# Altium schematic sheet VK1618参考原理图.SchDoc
size A4
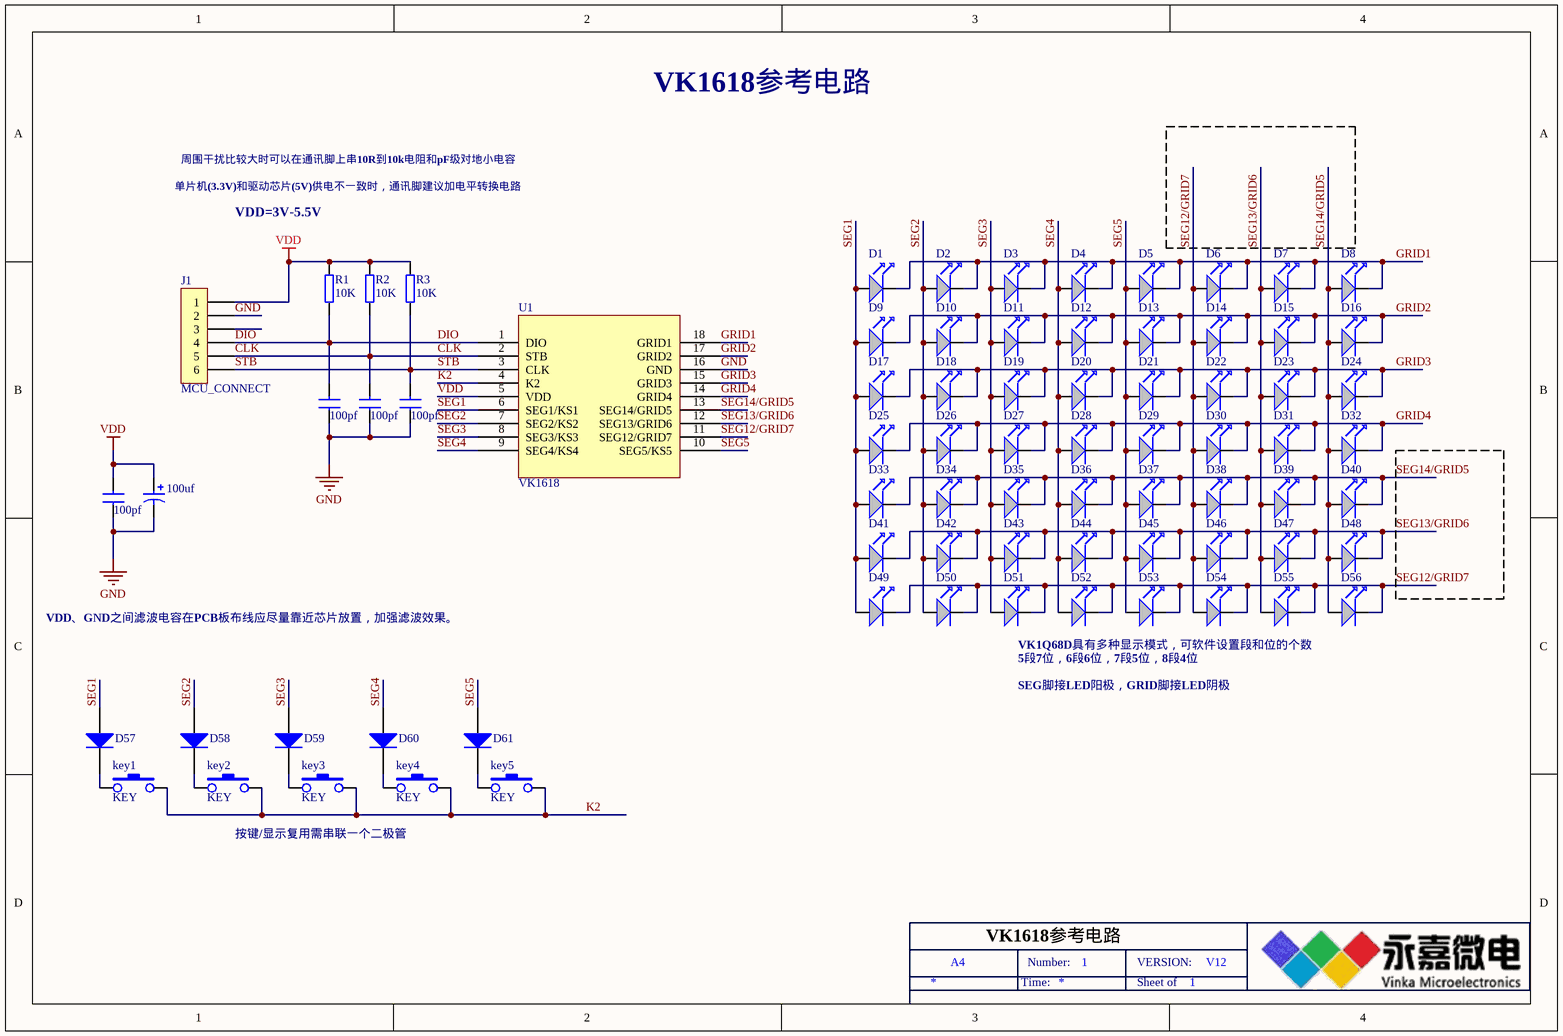
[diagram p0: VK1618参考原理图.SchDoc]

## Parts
100nf  100pf
100pf  CAP  (value not drawn)
100pf1  100pf
100pf3  100pf
100uf  CAP2  (value not drawn)
D1  (no value)  [1206-LED]
D2  (no value)  [1206-LED]
D3  (no value)  [1206-LED]
D4  (no value)  [1206-LED]
D5  (no value)  [1206-LED]
D6  (no value)  [1206-LED]
D7  (no value)  [1206-LED]
D8  (no value)  [1206-LED]
D9  (no value)  [1206-LED]
D10  (no value)  [1206-LED]
D11  (no value)  [1206-LED]
D12  (no value)  [1206-LED]
D13  (no value)  [1206-LED]
D14  (no value)  [1206-LED]
D15  (no value)  [1206-LED]
D16  (no value)  [1206-LED]
D17  (no value)  [1206-LED]
D18  (no value)  [1206-LED]
D19  (no value)  [1206-LED]
D20  (no value)  [1206-LED]
D21  (no value)  [1206-LED]
D22  (no value)  [1206-LED]
D23  (no value)  [1206-LED]
D24  (no value)  [1206-LED]
D25  (no value)  [1206-LED]
D26  (no value)  [1206-LED]
D27  (no value)  [1206-LED]
D28  (no value)  [1206-LED]
D29  (no value)  [1206-LED]
D30  (no value)  [1206-LED]
D31  (no value)  [1206-LED]
D32  (no value)  [1206-LED]
D33  (no value)  [1206-LED]
D34  (no value)  [1206-LED]
D35  (no value)  [1206-LED]
D36  (no value)  [1206-LED]
D37  (no value)  [1206-LED]
D38  (no value)  [1206-LED]
D39  (no value)  [1206-LED]
D40  (no value)  [1206-LED]
D41  (no value)  [1206-LED]
D42  (no value)  [1206-LED]
D43  (no value)  [1206-LED]
D44  (no value)  [1206-LED]
D45  (no value)  [1206-LED]
D46  (no value)  [1206-LED]
D47  (no value)  [1206-LED]
D48  (no value)  [1206-LED]
D49  (no value)  [1206-LED]
D50  (no value)  [1206-LED]
D51  (no value)  [1206-LED]
D52  (no value)  [1206-LED]
D53  (no value)  [1206-LED]
D54  (no value)  [1206-LED]
D55  (no value)  [1206-LED]
D56  (no value)  [1206-LED]
D57  Diode 1N4003  [DO-41]  (value not drawn)
D58  Diode 1N4003  [DO-41]  (value not drawn)
D59  Diode 1N4003  [DO-41]  (value not drawn)
D60  Diode 1N4003  [DO-41]  (value not drawn)
D61  Diode 1N4003  [DO-41]  (value not drawn)
J1  MCU_CONNECT
key1  KEY  [AN12]
key2  KEY  [AN12]
key3  KEY  [AN12]
key4  KEY  [AN12]
key5  KEY  [AN12]
R1  10K  [0603-R]
R2  10K  [0603-R]
R3  10K  [0603-R]
U1  VK1618

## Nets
GND: 100nf.2 100pf.2 100pf1.2 100pf3.2 100uf.2 J1.2 U1.16(GND)
VDD: 100nf.1 100uf.1 J1.1 R1.1 R2.1 R3.1 U1.5(VDD)
CLK: 100pf3.1 J1.5 R2.2 U1.2(STB)
DIO: 100pf1.1 J1.4 R1.2 U1.1(DIO)
GRID1: D1.2 D2.2 D3.2 D4.2 D5.2 D6.2 D7.2 D8.2 U1.18(GRID1)
GRID2: D9.2 D10.2 D11.2 D12.2 D13.2 D14.2 D15.2 D16.2 U1.17(GRID2)
GRID3: D17.2 D18.2 D19.2 D20.2 D21.2 D22.2 D23.2 D24.2 U1.15(GRID3)
GRID4: D25.2 D26.2 D27.2 D28.2 D29.2 D30.2 D31.2 D32.2 U1.14(GRID4)
K2: key1.2 key2.2 key3.2 key4.2 key5.2 U1.4(K2)
SEG1: D1.1 D9.1 D17.1 D25.1 D33.1 D41.1 D49.1 D57.1(A) U1.6(SEG1/KS1)
SEG2: D2.1 D10.1 D18.1 D26.1 D34.1 D42.1 D50.1 D58.1(A) U1.7(SEG2/KS2)
SEG3: D3.1 D11.1 D19.1 D27.1 D35.1 D43.1 D51.1 D59.1(A) U1.8(SEG3/KS3)
SEG4: D4.1 D12.1 D20.1 D28.1 D36.1 D44.1 D52.1 D60.1(A) U1.9(SEG4/KS4)
SEG5: D5.1 D13.1 D21.1 D29.1 D37.1 D45.1 D53.1 D61.1(A) U1.10(SEG5/KS5)
SEG12/GRID7: D6.1 D14.1 D22.1 D30.1 D38.1 D46.1 D49.2 D50.2 D51.2 D52.2 D53.2 D54.1 D54.2 D55.2 D56.2 U1.11(SEG12/GRID7)
SEG13/GRID6: D7.1 D15.1 D23.1 D31.1 D39.1 D41.2 D42.2 D43.2 D44.2 D45.2 D46.2 D47.1 D47.2 D48.2 D55.1 U1.12(SEG13/GRID6)
SEG14/GRID5: D8.1 D16.1 D24.1 D32.1 D33.2 D34.2 D35.2 D36.2 D37.2 D38.2 D39.2 D40.1 D40.2 D48.1 D56.1 U1.13(SEG14/GRID5)
STB: 100pf.1 J1.6 R3.2 U1.3(CLK)
NetD57_2: D57.2(K) key1.1
NetD58_2: D58.2(K) key2.1
NetD59_2: D59.2(K) key3.1
NetD60_2: D60.2(K) key4.1
NetD61_2: D61.2(K) key5.1

Not connected (* = marked no-connect by the designer): J1 3

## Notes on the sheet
- VK1618参考电路
- 周围干扰比较大时可以在通讯脚上串10R到10k电阻和pF级对地小电容
- 单片机(3.3V)和驱动芯片(5V)供电不一致时，通讯脚建议加电平转换电路
- VDD=3V-5.5V
- VDD、GND之间滤波电容在PCB板布线应尽量靠近芯片放置，加强滤波效果。
- VK1Q68D具有多种显示模式，可软件设置段和位的个数
- SEG脚接LED阳极，GRID脚接LED阴极
- 5段7位，6段6位，7段5位，8段4位
- 按键/显示复用需串联一个二极管
- A4
- Time:
- Number:
- 1
- Sheet of
- VERSION:
- V12

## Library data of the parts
100nf 100pf 100pf1 100pf3 = CAP: Capacitor
100uf = CAP2: Bi-Polar Capacitor
D1-D56 = LED: Text Field1: 30; Text Field2: 20
D57-D61 = Diode 1N4003: 1 Amp General Purpose Rectifier
J1 = CON6: Connector
R1-R3 = RES: Resistor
